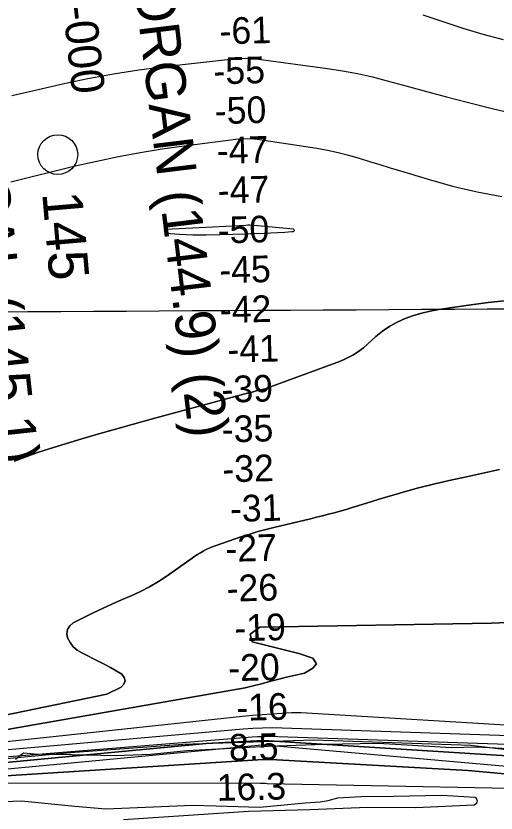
# Model space of a CAD drawing. Extents: x 3477039 to 3515015, y 546746 to 572297.
# Drawn here: x 3494436 to 3495642, y 563045 to 565048 of the extents above; entities that cross this region are included whole.
import ezdxf

# ---------------------------------------------------------------- set-up
doc = ezdxf.new("R2010")
doc.units = 0
for name, color, linetype in [('V-CHAN-NAID', 7, 'Continuous'), ('V-GRID-MAJR', 7, 'Continuous'), ('V-RIVR-EDGE', 7, 'Continuous'), ('V-RIVR-IDEN', 7, 'Continuous'), ('V-RIVR-MILE', 7, 'Continuous'), ('V-RIVR-RANG', 7, 'Continuous'), ('V-RIVR-RANG-IDEN', 7, 'Continuous'), ('V-RRAP-FSHR', 7, 'Continuous'), ('V-SITE-VEGE', 7, 'Continuous'), ('V-TOPO-DPTH', 7, 'Continuous'), ('V-TOPO-MAJR', 7, 'Continuous'), ('V-TOPO-MINR', 7, 'Continuous'), ('V-TOPO-WATR', 7, 'Continuous')]:
    doc.layers.add(name, color=color, linetype=linetype)

msp = doc.modelspace()

# ---------------------------------------------------------------- linework, layer by layer
at = {"layer": 'V-GRID-MAJR'}
msp.add_spline([(3481202, 564229.3), (3486474.8, 564258.8), (3491747.6, 564289.1), (3497020.4, 564320.1), (3502293.2, 564352), (3507566, 564384.6), (3512838.8, 564417.9)], degree=3, dxfattribs=at)
at = {"layer": 'V-RIVR-EDGE'}
msp.add_lwpolyline([(3494434.7, 563180.3), (3494455.2, 563196.5), (3494481.6, 563194), (3494577, 563192.6), (3494686.3, 563189.9), (3494775.1, 563193.3), (3494865.2, 563202.7), (3495069.4, 563213.6), (3495210.4, 563218.6), (3495345.5, 563220.7), (3495460.8, 563214.4), (3495529.8, 563210), (3495592.2, 563211.7), (3495769.3, 563202.8)], dxfattribs=at)
at = {"layer": 'V-RIVR-MILE'}
msp.add_circle((3494541.3, 564699.4), 50, dxfattribs=at)
at = {"layer": 'V-RRAP-FSHR'}
msp.add_lwpolyline([(3493227.5, 563039.2), (3493383.9, 563083.6), (3493544.7, 563110.8), (3493700.2, 563130.9), (3493831.3, 563136.3), (3493973.4, 563141), (3494573, 563197.4), (3494854.9, 563218.5), (3495183.7, 563229), (3495578.3, 563216.2), (3495899.2, 563176.4), (3496209.8, 563128.7), (3496976.7, 562924.4)], dxfattribs=at)
at = {"layer": 'V-SITE-VEGE'}
msp.add_lwpolyline([(3494384.4, 563073.9), (3494450.3, 563075.7), (3494584.3, 563063), (3494661.9, 563055.9), (3494781.3, 563060.9), (3494820.1, 563063), (3494879.5, 563064.9), (3494938.9, 563063.8), (3495048.9, 563060.1), (3495162.5, 563071), (3495200.1, 563073.1), (3495220.1, 563077), (3495244.3, 563083.3), (3495302.6, 563087), (3495385.5, 563087.6), (3495506.1, 563090.2), (3495588.4, 563085.4), (3495591.3, 563084.2), (3495594.2, 563076), (3495592.4, 563069), (3495586.5, 563064.9), (3495440.7, 563058.2), (3495320.2, 563059.6), (3495174.3, 563053.1), (3495020.2, 563049), (3494706.6, 563028.4)], dxfattribs=at)
at = {"layer": 'V-TOPO-DPTH'}
for points in [[(3494432.5, 563929.5), (3494461.4, 563940.4), (3494490.5, 563950.9), (3494519.9, 563960.6), (3494549.4, 563969.8), (3494585, 563980.4), (3494632.5, 563994.4), (3494680.1, 564008.1), (3494727.8, 564021.4), (3494775.6, 564034.5), (3495023.8, 564101.6), (3495029, 564102.9), (3495034.2, 564104.3), (3495039.4, 564105.6), (3495044.6, 564106.8), (3495051.3, 564108.3), (3495053.2, 564108.8), (3495055.1, 564109.2), (3495058.8, 564110.2), (3495062.6, 564111.2), (3495066.3, 564112.5), (3495242.3, 564177.1), (3495252.5, 564181.1), (3495262.5, 564185.5), (3495272.3, 564190.4), (3495281.9, 564195.6), (3495291.1, 564201.4), (3495300.1, 564207.5), (3495308.7, 564214.2), (3495317, 564221.3), (3495340, 564242.2), (3495356.9, 564256), (3495374.7, 564268.4), (3495393.7, 564278.7), (3495413.6, 564287.7), (3495434.3, 564294.9), (3495455.2, 564301.1), (3495476.6, 564306), (3495498.1, 564309.9), (3495566.4, 564320.1), (3495622.4, 564327.6), (3495678.5, 564334.1)], [(3495678.5, 564334.1), (3495622.4, 564327.6), (3495566.4, 564320.1), (3495498.1, 564309.9), (3495476.6, 564306), (3495455.2, 564301.1), (3495434.3, 564294.9), (3495413.6, 564287.7), (3495393.7, 564278.7), (3495374.7, 564268.4), (3495356.9, 564256), (3495340, 564242.2), (3495317, 564221.3), (3495308.7, 564214.2), (3495300.1, 564207.5), (3495291.1, 564201.4), (3495281.9, 564195.6), (3495272.3, 564190.4), (3495262.5, 564185.5), (3495252.5, 564181.1), (3495242.3, 564177.1), (3495066.3, 564112.5), (3495062.6, 564111.2), (3495058.8, 564110.2), (3495055.1, 564109.2), (3495053.2, 564108.8), (3495051.3, 564108.3), (3495044.6, 564106.8), (3495039.4, 564105.6), (3495034.2, 564104.3), (3495029, 564102.9), (3495023.8, 564101.6), (3494775.6, 564034.5), (3494727.8, 564021.4), (3494680.1, 564008.1), (3494632.5, 563994.4), (3494585, 563980.4), (3494549.4, 563969.8), (3494519.9, 563960.6), (3494490.5, 563950.9), (3494461.4, 563940.4), (3494432.5, 563929.5)], [(3494225.8, 563253.8), (3494664.8, 563344.1), (3494700.4, 563361.7), (3494707.4, 563369.4), (3494710.7, 563377.3), (3494708.2, 563385.5), (3494702, 563393.9), (3494687.9, 563402.4), (3494673.6, 563410.7), (3494659.1, 563418.5), (3494644.5, 563426.1), (3494601.3, 563447.5), (3494590.1, 563454.7), (3494580.2, 563463.2), (3494572.4, 563473.5), (3494565.9, 563485.2), (3494564.2, 563496.5), (3494565.5, 563506.7), (3494571.2, 563515.3), (3494579.9, 563522.8), (3494630.3, 563547.9), (3494653.8, 563559.3), (3494677.3, 563570.3), (3494701.2, 563580.8), (3494725.1, 563591), (3494748.8, 563601.7), (3494771.9, 563613.4), (3494794.1, 563626.6), (3494815.8, 563640.9), (3494878.8, 563685.6), (3494885.6, 563690.3), (3494892.5, 563694.8), (3494899.6, 563699.1), (3494906.7, 563703.2), (3494914, 563707), (3494921.4, 563710.5), (3494929, 563713.7), (3494936.7, 563716.6), (3495003.5, 563739.8), (3495023.3, 563746.3), (3495043.2, 563752.4), (3495063.3, 563757.9), (3495083.4, 563763), (3495175.7, 563784.8), (3495190.7, 563788.4), (3495205.7, 563792.1), (3495220.7, 563796), (3495235.6, 563799.9), (3495250.5, 563803.9), (3495265.4, 563808.1), (3495280.2, 563812.5), (3495294.9, 563817), (3495356.6, 563836.3), (3495400.1, 563849.2), (3495443.8, 563861.3), (3495487.8, 563872.2), (3495532, 563882.3), (3495560.1, 563888.3), (3495590.4, 563894.9), (3495620.7, 563901.4), (3495650.9, 563908)], [(3495650.9, 563908), (3495620.7, 563901.4), (3495590.4, 563894.9), (3495560.1, 563888.3), (3495532, 563882.3), (3495487.8, 563872.2), (3495443.8, 563861.3), (3495400.1, 563849.2), (3495356.6, 563836.3), (3495294.9, 563817), (3495280.2, 563812.5), (3495265.4, 563808.1), (3495250.5, 563803.9), (3495235.6, 563799.9), (3495220.7, 563796), (3495205.7, 563792.1), (3495190.7, 563788.4), (3495175.7, 563784.8), (3495083.4, 563763), (3495063.3, 563757.9), (3495043.2, 563752.4), (3495023.3, 563746.3), (3495003.5, 563739.8), (3494936.7, 563716.6), (3494929, 563713.7), (3494921.4, 563710.5), (3494914, 563707), (3494906.7, 563703.2), (3494899.6, 563699.1), (3494892.5, 563694.8), (3494885.6, 563690.3), (3494878.8, 563685.6), (3494815.8, 563640.9), (3494794.1, 563626.6), (3494771.9, 563613.4), (3494748.8, 563601.7), (3494725.1, 563591), (3494701.2, 563580.8), (3494677.3, 563570.3), (3494653.8, 563559.3), (3494630.3, 563547.9), (3494579.9, 563522.8), (3494571.2, 563515.3), (3494565.5, 563506.7), (3494564.2, 563496.5), (3494565.9, 563485.2), (3494572.4, 563473.5), (3494580.2, 563463.2), (3494590.1, 563454.7), (3494601.3, 563447.5), (3494644.5, 563426.1), (3494659.1, 563418.5), (3494673.6, 563410.7), (3494687.9, 563402.4), (3494702, 563393.9), (3494708.2, 563385.5), (3494710.7, 563377.3), (3494707.4, 563369.4), (3494700.4, 563361.7), (3494664.8, 563344.1), (3494225.8, 563253.8)], [(3495691, 563525.1), (3495630.6, 563522.7), (3495048.9, 563511.9), (3495024.5, 563494.5), (3495029, 563475.1), (3495146.7, 563446.2), (3495182.1, 563434.7), (3495191.2, 563419.8), (3495182, 563409.5), (3495160.4, 563396.7), (3495138.1, 563392), (3495116, 563386.7), (3495092.8, 563380.7), (3495072.6, 563375.5), (3495052.4, 563370.3), (3495032.1, 563365.3), (3495011.8, 563360.3), (3494259.8, 563228.7), (3494210.7, 563221.6), (3494161.6, 563214.8), (3494112.5, 563208.6), (3494063.3, 563202.7), (3493313.3, 563109.2), (3493194.2, 563088.6)], [(3495691, 563525.1), (3495630.6, 563522.7), (3495048.9, 563511.9), (3495024.5, 563494.5), (3495029, 563475.1), (3495146.7, 563446.2), (3495182.1, 563434.7), (3495191.2, 563419.8), (3495182, 563409.5), (3495160.4, 563396.7), (3495138.1, 563392), (3495116, 563386.7), (3495092.8, 563380.7), (3495072.6, 563375.5), (3495052.4, 563370.3), (3495032.1, 563365.3), (3495011.8, 563360.3), (3494259.8, 563228.7), (3494210.7, 563221.6), (3494161.6, 563214.8), (3494112.5, 563208.6), (3494063.3, 563202.7), (3493313.3, 563109.2), (3493194.2, 563088.6)], [(3493229.9, 563072.8), (3493252.5, 563075.3), (3493820.5, 563141.2), (3493878.2, 563147.9), (3493936, 563154.7), (3493993.7, 563161.5), (3494051.4, 563168.2), (3494098.9, 563173.8), (3494132.9, 563177.8), (3494166.9, 563181.7), (3494200.8, 563185.6), (3494234.8, 563189.4), (3495006.7, 563256.8), (3495030.9, 563258.4), (3495055.2, 563259.8), (3495079.5, 563260.6), (3495923.1, 563231.6), (3495938.8, 563230.3), (3495954.4, 563228.7), (3495970.1, 563226.7), (3495985.6, 563224.4), (3496773.6, 563066.8), (3496798.3, 563060.3), (3497514.4, 562885.9)], [(3493229.9, 563072.8), (3493252.5, 563075.3), (3493820.5, 563141.2), (3493878.2, 563147.9), (3493936, 563154.7), (3493993.7, 563161.5), (3494051.4, 563168.2), (3494098.9, 563173.8), (3494132.9, 563177.8), (3494166.9, 563181.7), (3494200.8, 563185.6), (3494234.8, 563189.4), (3495006.7, 563256.8), (3495030.9, 563258.4), (3495055.2, 563259.8), (3495079.5, 563260.6), (3495923.1, 563231.6), (3495938.8, 563230.3), (3495954.4, 563228.7), (3495970.1, 563226.7), (3495985.6, 563224.4), (3496773.6, 563066.8), (3496798.3, 563060.3), (3497514.4, 562885.9)], [(3496752.9, 563016.5), (3496022.1, 563159.1), (3495985.2, 563165.8), (3495948.2, 563171.9), (3495071.2, 563226.6), (3495063.6, 563226.8), (3495056, 563226.9), (3495048.4, 563226.7), (3495040.8, 563226.4), (3494914, 563219.8), (3494207.6, 563153.4), (3494189.8, 563151.5), (3494172, 563149.5), (3494154.2, 563147.4), (3494136.4, 563145.3), (3493929.2, 563119.9), (3493808, 563103.9), (3493687.1, 563086.3), (3493566.5, 563066.3), (3493446.2, 563044.8)], [(3493446.2, 563044.8), (3493566.5, 563066.3), (3493687.1, 563086.3), (3493808, 563103.9), (3493929.2, 563119.9), (3494136.4, 563145.3), (3494154.2, 563147.4), (3494172, 563149.5), (3494189.8, 563151.5), (3494207.6, 563153.4), (3494914, 563219.8), (3495040.8, 563226.4), (3495048.4, 563226.7), (3495056, 563226.9), (3495063.6, 563226.8), (3495071.2, 563226.6), (3495948.2, 563171.9), (3495985.2, 563165.8), (3496022.1, 563159.1), (3496752.9, 563016.5)], [(3496730.3, 562953.9), (3495961.8, 563115.2), (3495952.1, 563116.6), (3495942.4, 563117.9), (3495932.6, 563119.1), (3495922.8, 563120.1), (3495572, 563152.2), (3495091.7, 563179.4), (3495057.1, 563179.8), (3494185.3, 563124.3), (3494180.7, 563123.8), (3494176.1, 563123.3), (3494171.5, 563122.8), (3494166.9, 563122.2), (3493515.2, 563033.1)]]:
    msp.add_lwpolyline(points, dxfattribs=at)
at = {"layer": 'V-TOPO-MAJR'}
for points in [[(3494423.4, 564630.7), (3494477.2, 564644.6), (3494531.1, 564658), (3494585.2, 564670.8), (3494639.4, 564683.2), (3494693.8, 564694.5), (3494748.4, 564704.8), (3494803.2, 564713.5), (3494858.2, 564721.3), (3494988.4, 564737.8), (3495003.4, 564739.1), (3495018.3, 564739.5), (3495033.2, 564738.7), (3495048.1, 564737.1), (3495191.5, 564715.2), (3495218.3, 564710.4), (3495245, 564704.9), (3495271.4, 564698.2), (3495297.7, 564690.7), (3495323.7, 564682.5), (3495349.8, 564674.5), (3495375.9, 564666.4), (3495402.1, 564658.4), (3495471.4, 564637.3), (3495532.6, 564620.3), (3495594.2, 564605.7), (3495656.5, 564594.3)], [(3495135.7, 564509.1), (3495134.8, 564510.7), (3495132.9, 564512.2), (3495034.4, 564521.2), (3495029.1, 564521.6), (3495023.8, 564521.8), (3495018.4, 564521.8), (3495013.1, 564521.7), (3494812.9, 564511.3), (3494809.8, 564509), (3494808.4, 564506.7), (3494809.7, 564504.3), (3494812.7, 564501.9), (3494846.5, 564499.6), (3494880.2, 564498.1), (3494914, 564497.8), (3494947.8, 564498.4), (3495013.7, 564500.6), (3495019, 564500.8), (3495024.3, 564501), (3495029.6, 564501.2), (3495034.9, 564501.4), (3495059.2, 564502.3), (3495076.6, 564503), (3495094, 564503.8), (3495111.4, 564504.8), (3495128.8, 564505.9), (3495132.8, 564506.1), (3495134.8, 564507.6), (3495135.7, 564509.1)]]:
    msp.add_lwpolyline(points, dxfattribs=at)
at = {"layer": 'V-TOPO-MINR'}
for points in [[(3495458.1, 565050.7), (3495508.2, 565033.4), (3495558.4, 565017.1), (3495608.9, 565002.1), (3495660, 564988.9)], [(3494426.1, 564848.3), (3494480.8, 564860.7), (3494535.6, 564873.1), (3494553.1, 564877), (3494616.9, 564890.3), (3494680.8, 564902.2), (3494745.1, 564912), (3494809.7, 564920.4), (3494981.4, 564939.9), (3494997.3, 564941.1), (3495013.3, 564941.5), (3495029.2, 564940.8), (3495045.1, 564939.2), (3495218.7, 564915.9), (3495256.6, 564909.9), (3495294.3, 564903), (3495331.7, 564894.4), (3495368.8, 564884.8), (3495405.8, 564874.5), (3495442.8, 564864.4), (3495479.9, 564854.4), (3495517, 564844.5), (3495569.1, 564830.8), (3495632.4, 564814.9), (3495695.9, 564800.1)], [(3494432.5, 563929.5), (3494461.4, 563940.4), (3494490.5, 563950.9), (3494519.9, 563960.6), (3494549.4, 563969.8), (3494585, 563980.4), (3494632.5, 563994.4), (3494680.1, 564008.1), (3494727.8, 564021.4), (3494775.6, 564034.5), (3495023.8, 564101.6), (3495029, 564102.9), (3495034.2, 564104.3), (3495039.4, 564105.6), (3495044.6, 564106.8), (3495051.3, 564108.3), (3495053.2, 564108.8), (3495055.1, 564109.2), (3495058.8, 564110.2), (3495062.6, 564111.2), (3495066.3, 564112.5), (3495242.3, 564177.1), (3495252.5, 564181.1), (3495262.5, 564185.5), (3495272.3, 564190.4), (3495281.9, 564195.6), (3495291.1, 564201.4), (3495300.1, 564207.5), (3495308.7, 564214.2), (3495317, 564221.3), (3495340, 564242.2), (3495356.9, 564256), (3495374.7, 564268.4), (3495393.7, 564278.7), (3495413.6, 564287.7), (3495434.3, 564294.9), (3495455.2, 564301.1), (3495476.6, 564306), (3495498.1, 564309.9), (3495566.4, 564320.1), (3495622.4, 564327.6), (3495678.5, 564334.1)], [(3494225.8, 563253.8), (3494664.8, 563344.1), (3494700.4, 563361.7), (3494707.4, 563369.4), (3494710.7, 563377.3), (3494708.2, 563385.5), (3494702, 563393.9), (3494687.9, 563402.4), (3494673.6, 563410.7), (3494659.1, 563418.5), (3494644.5, 563426.1), (3494601.3, 563447.5), (3494590.1, 563454.7), (3494580.2, 563463.2), (3494572.4, 563473.5), (3494565.9, 563485.2), (3494564.2, 563496.5), (3494565.5, 563506.7), (3494571.2, 563515.3), (3494579.9, 563522.8), (3494630.3, 563547.9), (3494653.8, 563559.3), (3494677.3, 563570.3), (3494701.2, 563580.8), (3494725.1, 563591), (3494748.8, 563601.7), (3494771.9, 563613.4), (3494794.1, 563626.6), (3494815.8, 563640.9), (3494878.8, 563685.6), (3494885.6, 563690.3), (3494892.5, 563694.8), (3494899.6, 563699.1), (3494906.7, 563703.2), (3494914, 563707), (3494921.4, 563710.5), (3494929, 563713.7), (3494936.7, 563716.6), (3495003.5, 563739.8), (3495023.3, 563746.3), (3495043.2, 563752.4), (3495063.3, 563757.9), (3495083.4, 563763), (3495175.7, 563784.8), (3495190.7, 563788.4), (3495205.7, 563792.1), (3495220.7, 563796), (3495235.6, 563799.9), (3495250.5, 563803.9), (3495265.4, 563808.1), (3495280.2, 563812.5), (3495294.9, 563817), (3495356.6, 563836.3), (3495400.1, 563849.2), (3495443.8, 563861.3), (3495487.8, 563872.2), (3495532, 563882.3), (3495560.1, 563888.3), (3495590.4, 563894.9), (3495620.7, 563901.4), (3495650.9, 563908)], [(3493194.2, 563088.6), (3493313.3, 563109.2), (3494063.3, 563202.7), (3494112.5, 563208.6), (3494161.6, 563214.8), (3494210.7, 563221.6), (3494259.8, 563228.7), (3495011.8, 563360.3), (3495032.1, 563365.3), (3495052.4, 563370.3), (3495072.6, 563375.5), (3495092.8, 563380.7), (3495116, 563386.7), (3495138.1, 563392), (3495160.4, 563396.7), (3495182, 563409.5), (3495191.2, 563419.8), (3495182.1, 563434.7), (3495146.7, 563446.2), (3495029, 563475.1), (3495024.5, 563494.5), (3495048.9, 563511.9), (3495630.6, 563522.7), (3495691, 563525.1)], [(3494294.5, 563212.7), (3495005.3, 563288.6), (3495029.8, 563291), (3495054.4, 563293.2), (3495079, 563295), (3495103.6, 563296.6), (3495128.2, 563297.6), (3495152.8, 563297.9), (3495956.6, 563249.1)], [(3493229.9, 563072.8), (3493252.5, 563075.3), (3493820.5, 563141.2), (3493878.2, 563147.9), (3493936, 563154.7), (3493993.7, 563161.5), (3494051.4, 563168.2), (3494098.9, 563173.8), (3494132.9, 563177.8), (3494166.9, 563181.7), (3494200.8, 563185.6), (3494234.8, 563189.4), (3495006.7, 563256.8), (3495030.9, 563258.4), (3495055.2, 563259.8), (3495079.5, 563260.6), (3495923.1, 563231.6), (3495938.8, 563230.3), (3495954.4, 563228.7), (3495970.1, 563226.7), (3495985.6, 563224.4), (3496773.6, 563066.8), (3496798.3, 563060.3), (3497514.4, 562885.9)], [(3493235.1, 563014.9), (3493639, 563090.5), (3493903.4, 563133), (3493992, 563144.5), (3494117.7, 563159.5), (3494143.5, 563162.6), (3494169.4, 563165.6), (3494195.3, 563168.5), (3494221.2, 563171.3), (3495029.1, 563237), (3495042.4, 563237.7), (3495055.7, 563238), (3495069, 563238.1), (3495947, 563208.9), (3495952.2, 563208.3), (3495957.4, 563207.6), (3495962.6, 563206.8), (3496749.5, 563037)], [(3493463.6, 563037.7), (3493552.3, 563052.6), (3493641.3, 563065.8), (3493730.5, 563077.8), (3494155.1, 563131.1), (3494164.8, 563132.3), (3494174.5, 563133.4), (3495053.7, 563216.8), (3495056.2, 563216.9), (3495058.8, 563216.9), (3495061.3, 563216.8), (3495904.9, 563142.5), (3495924.7, 563140.3), (3495944.5, 563137.8), (3495964.3, 563134.9), (3496751.2, 562974.6)], [(3493515.2, 563033.1), (3494166.9, 563122.2), (3494171.5, 563122.8), (3494176.1, 563123.3), (3494180.7, 563123.8), (3494185.3, 563124.3), (3495057.1, 563179.8), (3495091.7, 563179.4), (3495572, 563152.2), (3495922.8, 563120.1), (3495932.6, 563119.1), (3495942.4, 563117.9), (3495952.1, 563116.6), (3495961.8, 563115.2), (3496730.3, 562953.9)], [(3493286.6, 562983.9), (3494174.8, 563116.3), (3494176, 563116.5), (3494179.6, 563116.9), (3494229.4, 563121.2), (3495050.6, 563120.1), (3495054.6, 563120.1), (3495058.6, 563120), (3495062.7, 563120), (3495066.7, 563119.9), (3495936.8, 563103), (3495940.7, 563102.6), (3495944.6, 563102), (3495973.6, 563097.4), (3495990, 563094.7), (3496006.4, 563091.7), (3496748.2, 562931.5)]]:
    msp.add_lwpolyline(points, dxfattribs=at)
at = {"layer": 'V-TOPO-WATR'}
msp.add_lwpolyline([(3493446.2, 563044.8), (3493566.5, 563066.3), (3493687.1, 563086.3), (3493808, 563103.9), (3493929.2, 563119.9), (3494136.4, 563145.3), (3494154.2, 563147.4), (3494172, 563149.5), (3494189.8, 563151.5), (3494207.6, 563153.4), (3494914, 563219.8), (3495040.8, 563226.4), (3495048.4, 563226.7), (3495056, 563226.9), (3495063.6, 563226.8), (3495071.2, 563226.6), (3495948.2, 563171.9), (3495985.2, 563165.8), (3496022.1, 563159.1), (3496752.9, 563016.5)], dxfattribs=at)

# ---------------------------------------------------------------- texts
at = {"layer": 'V-CHAN-NAID'}
for s, rotation, p in [('KINDER MORGAN (144.9) (2)', 276.9422, (3494653.4, 565777.1)), ('KAISER CHEMICAL (145.1)', 276.2606, (3494212.8, 565588.6))]:
    msp.add_text(s, height=100, rotation=rotation, dxfattribs=at).set_placement(p)
at = {"layer": 'V-RIVR-IDEN'}
msp.add_text('145', height=100, rotation=274.9271, dxfattribs=at).set_placement((3494502, 564602.6))
at = {"layer": 'V-RIVR-RANG'}
for s, rotation, p in [('-61', 1.5668, (3494948.2, 564976.2)), ('-55', 1.5668, (3494933, 564875.7)), ('-50', 1.5668, (3494936.3, 564775.8)), ('-47', 1.5668, (3494941.4, 564675.9)), ('-47', 1.5668, (3494943.9, 564575.9)), ('-50', 1.5668, (3494943.7, 564475.9)), ('-45', 1.5668, (3494947.5, 564375.9)), ('-42', 1.5668, (3494949, 564275.9)), ('-41', 1.5668, (3494968.1, 564176.4)), ('-39', 1.5668, (3494953.2, 564076)), ('-35', 1.5668, (3494953.8, 563975.9)), ('-32', 1.5668, (3494955.2, 563875.9)), ('-31', 1.5668, (3494974.3, 563776.4)), ('-27', 1.5668, (3494963.1, 563676.1)), ('-26', 1.5668, (3494965.9, 563576.1)), ('-19', 1.5668, (3494985.5, 563476.6)), ('-20', 1.5668, (3494970, 563376.2)), ('-16', 1.5668, (3494990.2, 563276.7)), ('8.5', 1.2883, (3494971.7, 563176.6)), ('16.3', 1.2883, (3494940.9, 563075.8))]:
    msp.add_text(s, height=67, rotation=rotation, dxfattribs=at).set_placement(p)
at = {"layer": 'V-RIVR-RANG-IDEN'}
msp.add_text('D-000', height=83, rotation=276.1963, dxfattribs=at).set_placement((3494545.4, 565149.1))

doc.saveas('drawing.dxf')
